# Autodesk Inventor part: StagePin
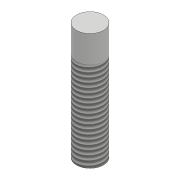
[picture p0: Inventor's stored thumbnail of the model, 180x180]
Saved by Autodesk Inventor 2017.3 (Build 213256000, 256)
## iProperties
Part Number: StagePin
Material: 一般
Document SubType Name: Modeling
Designer: kyushu-hep
Density: 1 g/cm^3
Appearance: 既定
Author: kyushu-hep
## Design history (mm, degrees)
sketch "スケッチ1"
  geometry: C1 r 1.5 at (0, 0); 1 further point
  constraints: 1 centre point, 1 coincident
  dimensions: "d0" = 3 diameter of C1
extrude "押し出し1" new body sketch "スケッチ1" distance "d1" = 13; taper "d2" = 0 deg
feature "ねじ1" dims "d3" = 10, "d4" = 0
node "ソリッド1"
